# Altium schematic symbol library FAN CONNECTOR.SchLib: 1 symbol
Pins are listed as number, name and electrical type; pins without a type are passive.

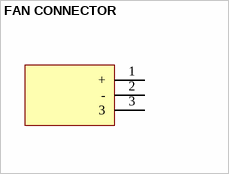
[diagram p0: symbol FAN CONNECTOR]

## FAN CONNECTOR
designator J?, comment Used in BOM report
SymbolVersion: use current date i.e. 2008-05-20; SymbolCreator: Use a-id; CompType: Used in some BOM reports.  Useful for finding later.; U/M: EA, IN, or GM
footprint FAN CONNECTOR
pins: 1 +, 2 -, 3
